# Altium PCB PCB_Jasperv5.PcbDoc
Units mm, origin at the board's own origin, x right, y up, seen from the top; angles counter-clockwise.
Board outline 98.63 x 43 mm, 2 copper layers (Top Layer, Bottom Layer); 4 components, 20 nets, 43 pads, 4 vias.
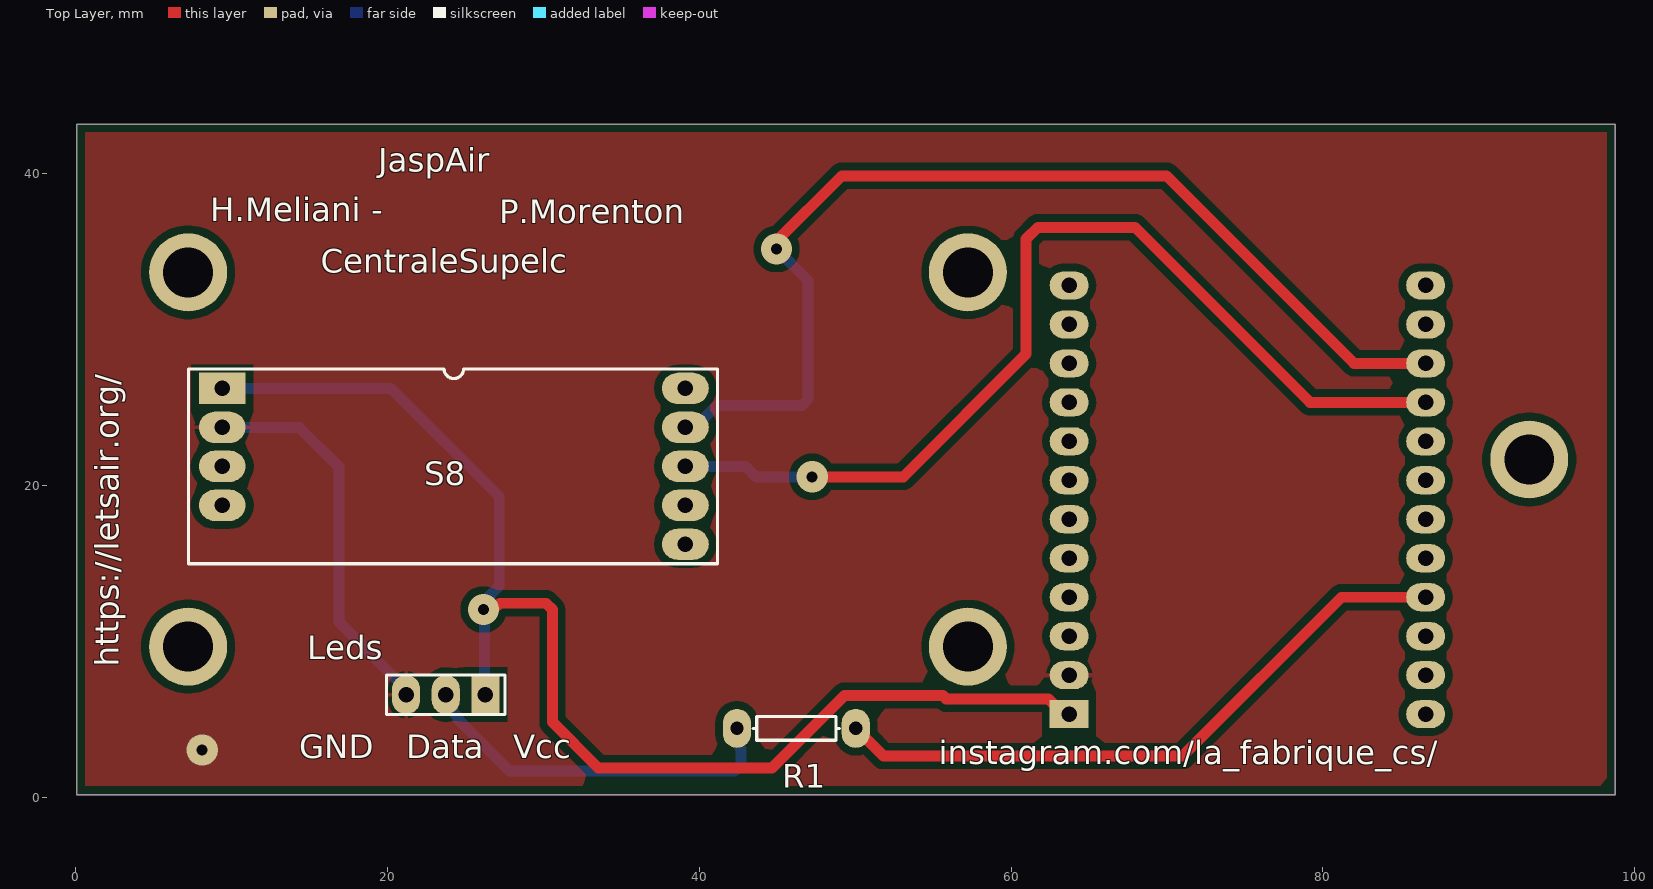
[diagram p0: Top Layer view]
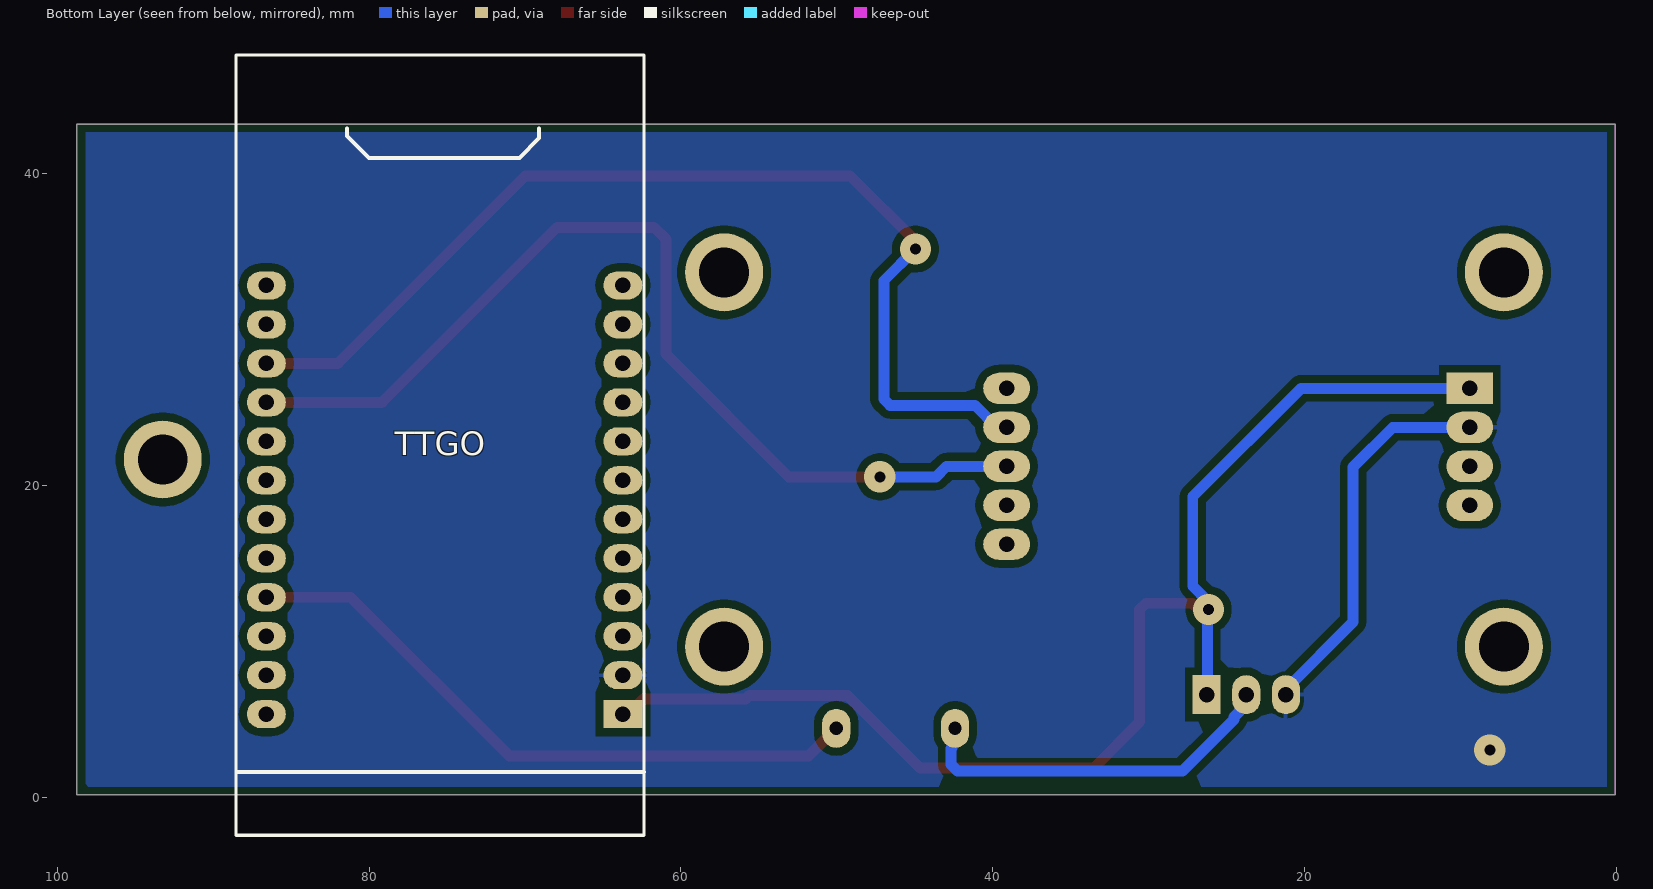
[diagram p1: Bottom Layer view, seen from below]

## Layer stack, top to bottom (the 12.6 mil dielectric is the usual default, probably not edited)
Top Solder: solder mask 0.0102, Solder Resist, Dk 3.5
Top Layer: signal copper 0.0356
Dielectric 1: dielectric 0.32, FR-4, Dk 4.8
Bottom Layer: signal copper 0.0356
Bottom Solder: solder mask 0.0102, Solder Resist, Dk 3.5

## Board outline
0.101,0.188 98.727,0.188 98.727,43.188 0.101,43.188

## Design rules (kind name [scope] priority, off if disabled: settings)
Clearance [All] p1: gap=0.5 ignorepadtopadclearanceinfootprint=FALSE
PolygonConnect [All] p1: connectstyle=Relief reliefconductorwidth=0.254 reliefentries=4 polygonreliefangle="90 Angle" airgapwidth=0.254
RoutingVias [All] p1: holewidth=0.711 width=2 viastyle="Through Hole" minholewidth=0.711 minwidth=2 maxholewidth=0.711 maxwidth=2
SolderMaskExpansion [All] p1: expansion=0.102 istentingtop=FALSE
SupplyNets "Schematic Supply Nets_1" [InNet('GND')] p1: voltage=0.000
SupplyNets "Schematic Supply Nets" [InNet('VCC')] p2: voltage=0.000
Width [All] p1: maxlimit=0.7 minlimit=0.7 preferedwidth=0.7
30 further rules are at their usual default settings.

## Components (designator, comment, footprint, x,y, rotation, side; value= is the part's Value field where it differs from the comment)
Leds "Header 3" HDR1X3 26.289,6.604 r180 top
R1 "Res1" AXIAL-0.3 46.228,4.445 r180 top value=470
S8 "S8" S8 9.416,26.249 r0 top
TTGO "Component_1" TTGO 62.103,47.879 r0 bottom

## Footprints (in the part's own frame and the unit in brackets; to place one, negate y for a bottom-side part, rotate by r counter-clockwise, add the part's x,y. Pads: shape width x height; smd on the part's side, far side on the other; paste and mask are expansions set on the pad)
AXIAL-0.3 [mm] "Axial Device, Thru-Hole; 2 Leads; 0.3 in Pin Spacing"
  oval 1.8x2.5 hole 0.85: 1(-3.81,0) 2(3.81,0)
  silkscreen extent -2.77,-0.76 2.77,0.76
HDR1X3 [mm] "Connector; Header; 3 Position"
  rect 1.8x2.5 hole 1: 1(0,0)
  oval 1.8x2.5 hole 1: 2(2.54,0) 3(5.08,0)
  silkscreen extent -1.27,-1.27 6.35,1.27
S8 [mm]
  rect 3x2 hole 1: 1(0,0)
  oval 3x2 hole 1: 2(0,-2.5) 3(0,-5) 4(0,-7.5) 5(29.7,-10) 6(29.7,-7.5) 7(29.7,-5) 8(29.7,-2.5) 9(29.7,0)
  silkscreen extent -2.16,-11.25 31.75,1.25, body extent -2.92,-12.45 31.37,4.57, height 9.8
TTGO [mm]
  rect 2.5x1.8 hole 1: 1(1.622,42.526)
  oval 2.5x1.8 hole 1: 2(1.622,40.026) 3(1.622,37.526) 4(1.622,35.026) 5(1.622,32.526) 6(1.622,30.026) 7(1.622,27.526) 8(1.622,25.026) 9(1.622,22.526) 10(1.622,20.026) 11(1.622,17.526) 12(1.622,15.026) 13(24.48,42.526) 14(24.48,40.026) 15(24.48,37.526) 16(24.48,35.026) 17(24.48,32.526) 18(24.48,30.026) 19(24.48,27.526) 20(24.48,25.026) 21(24.48,22.526) 22(24.48,20.026) 23(24.48,17.526) 24(24.48,15.026)
  silkscreen extent 0.25,0.25 26.42,50.29

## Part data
Leds: library part CMP-012-000090-1, "Header, 3-Pin"
R1: library part CMP-025-000011-1, "Resistor"

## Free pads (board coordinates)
  round 5 hole 3.2: 2(7.227,9.688) 2(7.227,33.688) 2(57.227,9.688) 2(57.227,33.688) 2(93.227,21.688)

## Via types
v1: diameter 2, hole 0.711, Top Layer to Bottom Layer, 4 vias

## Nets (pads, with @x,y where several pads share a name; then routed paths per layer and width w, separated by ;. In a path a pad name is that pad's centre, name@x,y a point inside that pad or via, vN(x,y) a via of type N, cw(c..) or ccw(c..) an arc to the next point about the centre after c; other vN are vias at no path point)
3V3: TTGO.12
GND: Leds.3 S8.2 TTGO.2 | length 24.9
  Bottom Layer w0.7: S8.2 14.351,23.749 16.891,21.209 16.891,11.272 21.209,6.954 Leds.3
  other v1: 8.128,3.048
NetLeds_2: Leds.2 R1.2 | length 24.4
  Bottom Layer w0.7: Leds.2 23.749,5.956 24.539,5.166 24.539,5.002 27.835,1.706 42.262,1.706 42.672,2.116 42.672,3.135 42.628,3.178 42.628,4.866 R1.2@42.672,4.91
P2: TTGO.19
P12: R1.1 TTGO.16 | length 41.5
  Top Layer w0.7: R1.1 50.038,4.393 50.546,3.885 50.598,3.885 51.816,2.667 70.993,2.667 81.179,12.853 TTGO.16
P13: TTGO.17
P15: TTGO.18
P17: TTGO.20
P25: TTGO.5
P26: TTGO.4
P27: TTGO.3
P32: TTGO.7
P33: TTGO.6
P36: TTGO.11
P37: TTGO.10
P38: TTGO.9
P39: TTGO.8
Rx: S8.8 TTGO.22 | length 67.6
  Top Layer w0.7: v1@44.831,35.56 49.149,39.878 69.977,39.878 82.002,27.853 TTGO.22
  Bottom Layer w0.7: S8.8 39.732,23.749 41.129,25.146 46.58,25.146 46.99,25.556 46.99,33.147 v1(44.958,35.179)
Tx: S8.7 TTGO.21 | length 63.3
  Top Layer w0.7: v1(47.244,20.574) 53.086,20.574 60.96,28.448 60.96,35.814 61.722,36.576 67.945,36.576 79.168,25.353 TTGO.21
  Bottom Layer w0.7: S8.7 42.968,21.249 43.643,20.574 v1(47.244,20.574)
VCC: Leds.1 S8.1 TTGO.1 | length 82.7
  Top Layer w0.7: v1(26.162,12.065) 26.411,12.314 27.069,12.314 27.222,12.467 30.176,12.467 30.586,12.056 30.586,4.847 33.528,1.905 44.673,1.905 49.313,6.545 55.632,6.545 55.839,6.338 62.39,6.338 63.375,5.353 TTGO.1
  Bottom Layer w0.7: S8.1 20.233,26.249 27.178,19.304 27.178,13.574 26.289,12.685 v1@26.289,11.938 ; v1(26.162,12.065) v1@26.289,11.938 ; Leds.1 26.226,6.667 26.226,11.874 v1@26.289,11.938
pads on no net: S8.3 S8.4 S8.5 S8.6 S8.9 TTGO.13 TTGO.14 TTGO.15 TTGO.23 TTGO.24

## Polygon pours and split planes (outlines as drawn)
GND on Top Layer "GND_L01_P000" (solid, pour order 0): 0,43.18 0.127,43.053 98.552,43.053 98.552,0.254 98.425,0.127 97.79,0.762 -0.127,0.762 -0.127,43.434
GND on Bottom Layer "GND_L02_P001" (solid, pour order 1): 0.254,42.799 98.171,42.799 98.171,0.889 97.663,0.381 0.254,0.381 0.254,42.926 0.381,43.053

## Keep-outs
Keep-Out Layer:
  the board outline again, w0.03

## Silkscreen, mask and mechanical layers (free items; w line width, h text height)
Top Overlay:
  text "JaspAir" at 19.431,40.132 h1.52
  text "H.Meliani -" at 8.636,36.957 h1.52
  text "P.Morenton" at 27.178,36.83 h1.52
  text "CentraleSupelc" at 15.748,33.655 h1.52
  text "https://letsair.org/" at 2.794,8.382 h1.52 r90
  text "GND" at 14.351,2.54 h1.52
  text "Data" at 21.209,2.54 h1.52
  text "Vcc" at 28.067,2.54 h1.52
  text "instagram.com/la_fabrique_cs/" at 55.372,2.159 h1.52
Bottom Overlay:
  lines w0.254: 69.088,42.926 69.088,42.291 70.358,41.021 80.01,41.021 81.407,42.418 81.407,42.926
Mechanical 1:
  circle w0.13: c7.248,9.648 r3.5
  circle w0.13: c7.248,9.648 r1.15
